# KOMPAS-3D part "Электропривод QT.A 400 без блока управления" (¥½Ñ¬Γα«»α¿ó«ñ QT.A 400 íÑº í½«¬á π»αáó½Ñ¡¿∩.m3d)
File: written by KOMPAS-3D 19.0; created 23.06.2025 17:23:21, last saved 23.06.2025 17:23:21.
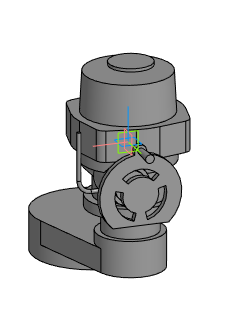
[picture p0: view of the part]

Document properties: Автор: Евгений; Полное имя файла: E:\Dendor Работа Сачек\3D для проектировщиков\3.5 Тип QT.А Электропривод\stp_Электропривод QT.A без блока управления\Электропривод QT.A 400 без блока управления.m3d

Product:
- Part/product: Электропривод QT.A 400 без блока управления

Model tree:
1. Операция без истории:1  (labels: Электропривод QT.A 400 без блока управления)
